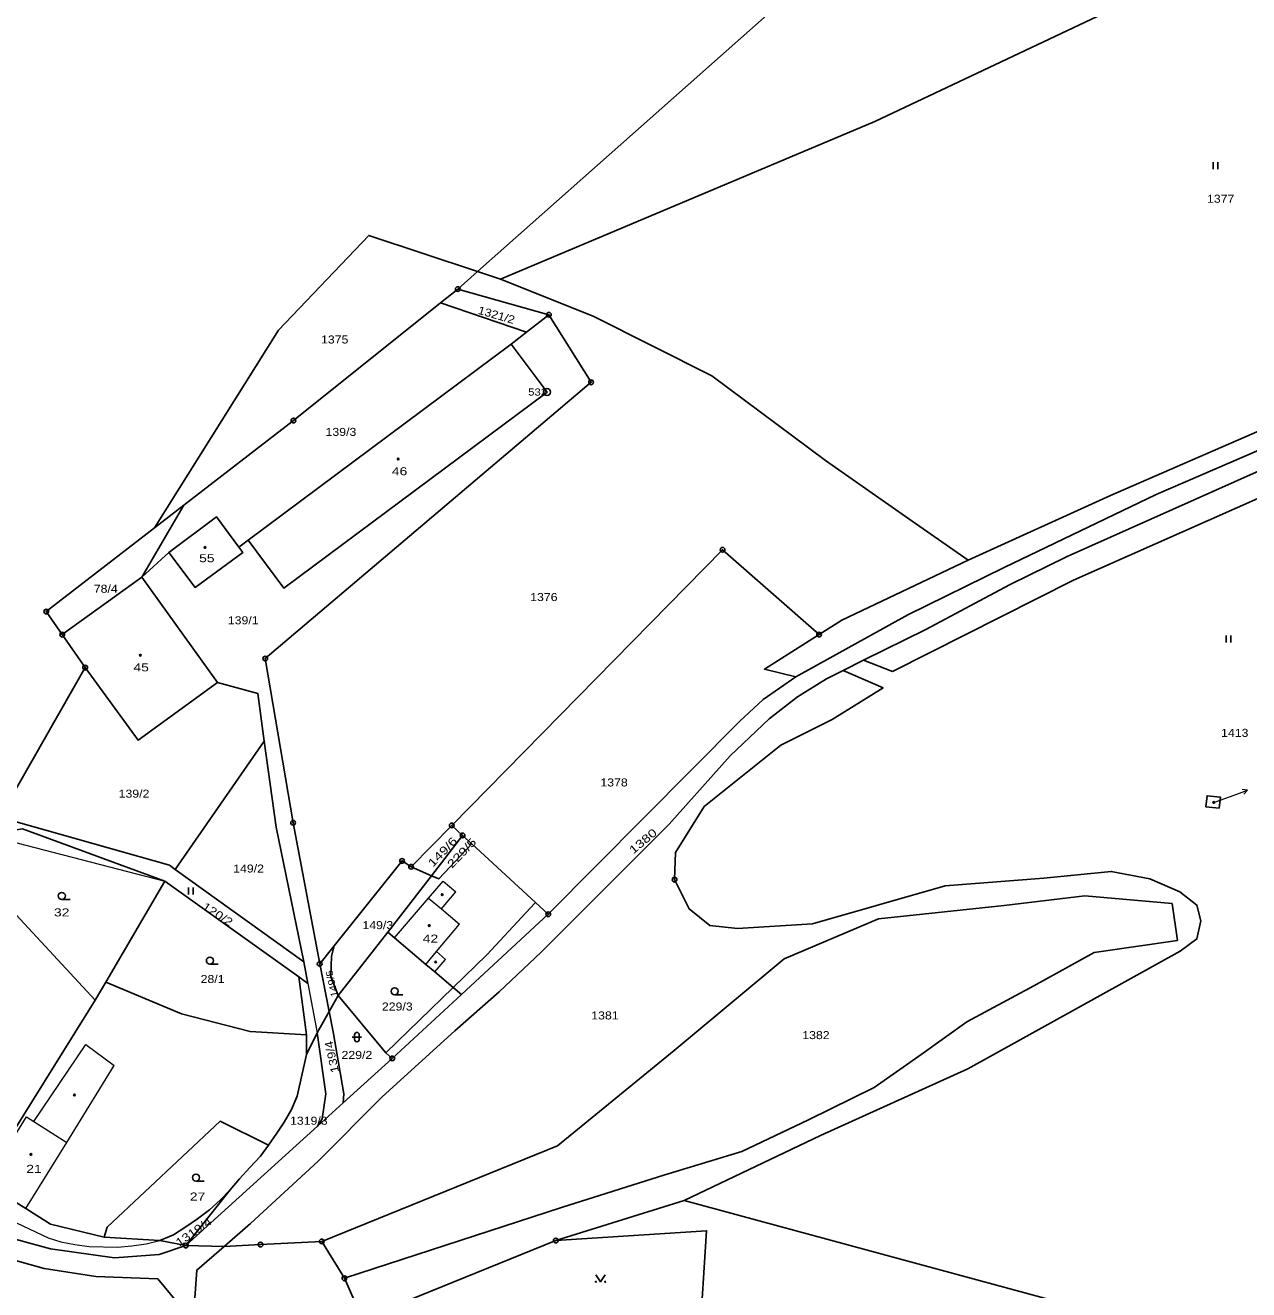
# Model space of a CAD drawing. Extents: x -872229 to -869198, y -1075981 to -1074329.
# Drawn here: x -870924.3 to -870664.3, y -1075205 to -1074936.4 of the extents above; entities that cross this region are included whole.
import ezdxf
from ezdxf.enums import TextEntityAlignment as Align

# ---------------------------------------------------------------- set-up
doc = ezdxf.new("R2010")
doc.units = 0
doc.header["$LTSCALE"] = 0.68
for name, color, linetype, lineweight in [('1', 7, 'Continuous', 25), ('3', 7, 'Continuous', 25), ('4', 7, 'Continuous', 13), ('5', 7, 'Continuous', 25), ('7', 7, 'Continuous', 13), ('8', 7, 'Continuous', 25)]:
    doc.layers.add(name, color=color, linetype=linetype, lineweight=lineweight)
doc.layers.add('2', color=7, linetype='Continuous')

msp = doc.modelspace()

# ---------------------------------------------------------------- linework, layer by layer
at = {"layer": '1'}
for p, q in [((-870832.43, -1074992.44), (-870828.23, -1074988.72)), ((-870828.23, -1074988.72), (-870823.34, -1074990.34)), ((-870832.43, -1074992.44), (-870813.05, -1074997.9)), ((-870817.8, -1075001.55), (-870836.08, -1074995.36)), ((-870821.1, -1075004.1), (-870876.96, -1075045.75)), ((-870890.62, -1075038.35), (-870899.54, -1075053.64)), ((-870896.85, -1075043.16), (-870890.62, -1075038.35)), ((-870876.96, -1075045.75), (-870878.94, -1075047.23)), ((-870893.79, -1075048.39), (-870899.54, -1075053.64)), ((-870916.45, -1075065.85), (-870911.59, -1075072.86)), ((-870837.98, -1075117.09), (-870831.39, -1075108.5)), ((-870892.44, -1075115.73), (-870865.1, -1075135.39)), ((-870837.98, -1075117.09), (-870842.32, -1075115.15)), ((-870857.82, -1075142.49), (-870847.25, -1075129.09)), ((-870858.7, -1075131.95), (-870861.76, -1075135.78)), ((-870907.21, -1075139.69), (-870909.44, -1075143.5)), ((-870857.82, -1075142.49), (-870859.76, -1075145.91)), ((-870856.75, -1075165.32), (-870846.32, -1075155.87)), ((-870862.22, -1075170.28), (-870856.75, -1075165.32)), ((-870890.21, -1075195.64), (-870862.22, -1075170.28)), ((-870880.8, -1075183.78), (-870890.21, -1075195.64)), ((-870784.32, -1075186.07), (-870610.3, -1075233.15)), ((-870907.54, -1075193.83), (-870895.75, -1075194.57)), ((-870895.75, -1075194.57), (-870890.21, -1075195.64)), ((-870890.21, -1075195.64), (-870882.08, -1075195.84)), ((-870856.49, -1075202.6), (-870861.31, -1075194.77))]:
    msp.add_line(p, q, dxfattribs=at)
for points in [[(-870828.23, -1074988.72), (-870733.1, -1074904.34), (-870634.05, -1074816.48)], [(-870823.34, -1074990.34), (-870743.76, -1074956.82), (-870646.76, -1074910.9), (-870624.12, -1074897.23)], [(-870723.96, -1075050), (-870693.71, -1075036.28), (-870649.55, -1075017.06), (-870584.14, -1074987.8), (-870552.32, -1074975.37), (-870546.15, -1074971.5), (-870542.19, -1074967.42)], [(-870896.85, -1075043.16), (-870870.5, -1075001.16), (-870851.34, -1074981.04), (-870828.23, -1074988.72)], [(-870760.55, -1075074.8), (-870736.8, -1075061.65), (-870716.28, -1075051.57), (-870684.01, -1075036.04), (-870643.52, -1075018.55), (-870612.61, -1075004.24), (-870591.23, -1074994.43), (-870570.04, -1074985.9), (-870558.3, -1074982.28), (-870544.73, -1074980.25)], [(-870746.19, -1075071.27), (-870732.98, -1075064.74), (-870715.15, -1075055.28), (-870702.93, -1075049.25), (-870662.75, -1075031.31), (-870646.95, -1075024.02), (-870627.8, -1075016.08), (-870598.46, -1075002.7), (-870582.08, -1074994.97), (-870575.53, -1074992.25), (-870561.97, -1074987.44), (-870555.39, -1074985.35), (-870547.72, -1074984.42), (-870543.16, -1074984.27), (-870536.54, -1074984.58), (-870532.83, -1074984.88), (-870528.68, -1074985.73), (-870515.43, -1074988.43), (-870489.43, -1074993.61), (-870451.62, -1074998.98)], [(-870723.96, -1075050), (-870735.85, -1075041.72), (-870754.24, -1075028.86), (-870778.4, -1075010.85), (-870803.61, -1074998.16), (-870823.34, -1074990.34)], [(-870890.62, -1075038.35), (-870867.33, -1075020.36), (-870836.08, -1074995.36), (-870832.43, -1074992.44)], [(-870861.76, -1075135.78), (-870867.42, -1075105.8), (-870873.32, -1075070.92), (-870804.09, -1075012.24), (-870813.05, -1074997.9), (-870817.8, -1075001.55), (-870821.1, -1075004.1)], [(-870876.96, -1075045.75), (-870869.36, -1075056), (-870813.44, -1075014.3), (-870821.1, -1075004.1)], [(-870746.19, -1075071.27), (-870740.01, -1075073.65), (-870701.56, -1075054.27), (-870661.14, -1075036.37), (-870626.13, -1075019.06), (-870610.36, -1075011.6)], [(-870916.45, -1075065.85), (-870919.85, -1075060.95), (-870896.85, -1075043.16)], [(-870878.94, -1075047.23), (-870883.7, -1075040.81), (-870893.79, -1075048.39)], [(-870893.79, -1075048.39), (-870888.25, -1075055.83), (-870878.08, -1075048.38), (-870878.94, -1075047.23)], [(-870833.7, -1075106.39), (-870776.15, -1075047.82), (-870755.65, -1075065.84)], [(-870755.65, -1075065.84), (-870750.79, -1075062.78), (-870723.96, -1075050)], [(-870911.59, -1075072.86), (-870900.34, -1075088.23), (-870883.44, -1075076.03), (-870899.54, -1075053.64), (-870916.45, -1075065.85)], [(-870760.55, -1075074.8), (-870767.27, -1075073.18), (-870755.65, -1075065.84)], [(-870882.08, -1075195.84), (-870876.48, -1075190.98), (-870862.11, -1075177.7), (-870848.46, -1075164.05), (-870833.06, -1075150.02), (-870823.61, -1075141.72), (-870814.66, -1075133.34), (-870787.51, -1075106.14), (-870774.51, -1075091.61), (-870766.24, -1075083.76), (-870760.23, -1075079.03), (-870754.08, -1075075.24), (-870750.53, -1075073.45), (-870746.19, -1075071.27)], [(-870930.06, -1075104.56), (-870928.47, -1075102.44), (-870911.59, -1075072.86)], [(-870813.18, -1075125.26), (-870772.47, -1075084.22), (-870767.49, -1075079.65), (-870760.55, -1075074.8)], [(-870784.32, -1075186.07), (-870755.33, -1075172.29), (-870724.06, -1075158.07), (-870678.88, -1075133.11), (-870675.36, -1075130.49), (-870674.52, -1075126.66), (-870675.34, -1075123.32), (-870678.97, -1075120.49), (-870685.35, -1075117.73), (-870693.57, -1075116.15), (-870707.89, -1075117.61), (-870728.84, -1075119.23), (-870757.05, -1075127.29), (-870772.94, -1075128.29), (-870778.87, -1075127.61), (-870783.25, -1075124.12), (-870786.34, -1075117.9), (-870786.18, -1075112.16), (-870780.09, -1075102.34), (-870763.77, -1075089.36), (-870752.86, -1075083.85), (-870742.03, -1075077.18), (-870750.53, -1075073.45)], [(-870883.44, -1075076.03), (-870874.9, -1075078.35), (-870873.52, -1075088.47)], [(-870930.06, -1075104.56), (-870893.7, -1075114.82), (-870892.44, -1075115.73), (-870873.52, -1075088.47)], [(-870873.52, -1075088.47), (-870871.03, -1075106.76), (-870865.1, -1075135.39)], [(-870894.66, -1075118.2), (-870924.88, -1075107.13), (-870932.92, -1075108.35)], [(-870858.7, -1075131.95), (-870844.26, -1075113.92), (-870842.32, -1075115.15), (-870833.7, -1075106.39)], [(-870833.7, -1075106.39), (-870831.39, -1075108.5), (-870829.44, -1075110.29)], [(-870829.44, -1075110.29), (-870836.42, -1075117.76), (-870837.98, -1075117.09)], [(-870829.44, -1075110.29), (-870815.89, -1075122.76), (-870813.18, -1075125.26)], [(-870864.56, -1075150.9), (-870866.19, -1075138.58), (-870894.66, -1075118.2), (-870907.21, -1075139.69)], [(-870837.98, -1075117.09), (-870847.25, -1075129.09), (-870845.84, -1075130.29)], [(-870909.44, -1075143.5), (-870927.17, -1075124.39), (-870932.72, -1075121.96), (-870936.66, -1075131.14), (-870945.89, -1075145.67), (-870949.71, -1075143.97), (-870951.3, -1075148.19), (-870958.37, -1075166.98), (-870949.29, -1075170.31), (-870949.89, -1075171.55)], [(-870861.31, -1075194.77), (-870811.22, -1075174.45), (-870786.41, -1075154.2), (-870763.05, -1075134.75), (-870742.98, -1075126.21), (-870716.31, -1075123.38), (-870699.19, -1075121.37), (-870680.62, -1075122.97), (-870679.5, -1075130.81), (-870697.18, -1075133.41), (-870710, -1075140.48), (-870724.25, -1075148.13), (-870733.72, -1075154.9), (-870743.9, -1075162.08), (-870757.91, -1075168.9), (-870772.04, -1075175.68), (-870788.41, -1075180.62), (-870810.37, -1075187.53), (-870856.49, -1075202.6)], [(-870813.18, -1075125.26), (-870831.64, -1075142.31), (-870846.32, -1075155.87)], [(-870845.84, -1075130.29), (-870839.22, -1075135.9), (-870837.31, -1075137.51), (-870833.4, -1075140.82), (-870831.64, -1075142.31)], [(-870857.82, -1075142.49), (-870859.36, -1075138.42), (-870859.25, -1075134.15), (-870858.7, -1075131.95)], [(-870865.1, -1075135.39), (-870864.25, -1075139.97), (-870866.19, -1075138.58)], [(-870864.56, -1075150.9), (-870864.55, -1075155.07), (-870862.32, -1075150.43), (-870859.76, -1075145.91), (-870861.76, -1075135.78)], [(-870907.21, -1075139.69), (-870891.11, -1075146.44), (-870876.55, -1075150.17), (-870864.56, -1075150.9)], [(-870846.32, -1075155.87), (-870847.68, -1075154.69), (-870857.82, -1075142.49)], [(-870949.89, -1075171.55), (-870931.15, -1075178.18), (-870909.44, -1075143.5)], [(-870856.75, -1075165.32), (-870856.65, -1075163.41), (-870858.9, -1075150.23), (-870859.76, -1075145.91)], [(-870862.32, -1075150.43), (-870860.42, -1075163.37), (-870861.23, -1075168.69), (-870862.22, -1075170.28)], [(-870890.21, -1075195.64), (-870895.9, -1075197.55), (-870905.34, -1075198.25), (-870918.98, -1075196.32), (-870930.4, -1075193.2), (-870939.76, -1075189.14), (-870966.78, -1075174.22), (-871004.43, -1075162.38), (-871023.49, -1075157.84), (-871022.7, -1075155.06)], [(-870864.55, -1075155.07), (-870866.56, -1075163.88), (-870867.75, -1075166.75), (-870869.33, -1075169.39), (-870870.88, -1075171.78), (-870872.64, -1075174.34)], [(-870907.54, -1075193.83), (-870906.89, -1075191.76), (-870882.9, -1075169.23), (-870872.64, -1075174.34)], [(-870872.64, -1075174.34), (-870874.32, -1075176.63), (-870876.57, -1075179.07), (-870878.78, -1075181.49), (-870880.8, -1075183.78)], [(-870931.15, -1075178.18), (-870930.37, -1075178.46), (-870932.82, -1075182.43), (-870924.17, -1075187.79)], [(-870880.8, -1075183.78), (-870882.93, -1075186.01), (-870885.17, -1075188.02), (-870887.7, -1075189.96), (-870890.19, -1075191.67), (-870892.85, -1075193.36), (-870895.75, -1075194.57)], [(-870924.17, -1075187.79), (-870918.98, -1075191.1), (-870907.54, -1075193.83)], [(-870852.61, -1075211.21), (-870811.58, -1075194.57), (-870784.32, -1075186.07)], [(-870811.58, -1075194.57), (-870779.53, -1075192.5), (-870781.56, -1075223.68)], [(-870882.08, -1075195.84), (-870887.87, -1075200.84), (-870890.54, -1075238.17)], [(-870861.31, -1075194.77), (-870874.33, -1075195.43), (-870882.08, -1075195.84)], [(-870925.85, -1075268.83), (-870908.47, -1075274.58), (-870898.66, -1075275.61), (-870893.76, -1075273.35), (-870892.7, -1075270.97), (-870894.88, -1075238.8), (-870892.1, -1075207.59), (-870896.18, -1075202.7), (-870909.34, -1075202.24), (-870920.27, -1075200.54), (-870931.8, -1075197.32)], [(-870852.61, -1075211.21), (-870854.23, -1075207.71), (-870856.49, -1075202.6)]]:
    msp.add_lwpolyline(points, dxfattribs=at)
msp.add_lwpolyline([(-870670.61, -1075102.74), (-870670.36, -1075100.35), (-870673.18, -1075100.06), (-870673.43, -1075102.45)], close=True, dxfattribs=at)
at = {"layer": '3'}
for p, q in [((-870671.891, -1074966.97), (-870671.891, -1074965.47)), ((-870670.89, -1074966.97), (-870670.89, -1074965.47)), ((-870669.151, -1075067.5), (-870669.151, -1075066)), ((-870668.15, -1075067.5), (-870668.15, -1075066)), ((-870889.631, -1075121.08), (-870889.631, -1075119.58)), ((-870888.63, -1075121.08), (-870888.63, -1075119.58)), ((-870916.553, -1075122.11), (-870914.803, -1075122.11)), ((-870885.093, -1075135.85), (-870883.343, -1075135.85)), ((-870845.823, -1075142.37), (-870844.073, -1075142.37)), ((-870854.861, -1075151.341), (-870852.859, -1075151.341)), ((-870854.361, -1075150.841), (-870854.361, -1075151.842)), ((-870853.359, -1075151.842), (-870853.359, -1075150.841)), ((-870888.033, -1075181.95), (-870886.283, -1075181.95))]:
    msp.add_line(p, q, dxfattribs=at)
msp.add_lwpolyline([(-870803.07, -1075201.839), (-870802.07, -1075203.34), (-870801.07, -1075201.839)], dxfattribs=at)
for centre, radius in [((-870916.5529, -1075121.3598), 0.75), ((-870885.0929, -1075135.0998), 0.75), ((-870845.8229, -1075141.6198), 0.75), ((-870888.0329, -1075181.1998), 0.75), ((-870803.07, -1075203.3395), 0.1), ((-870801.07, -1075203.3395), 0.1)]:
    msp.add_circle(centre, radius, dxfattribs=at)
for centre, start, end in [((-870853.86, -1075150.8409), 0, 180), ((-870853.86, -1075151.8409), 180, 359.98789)]:
    msp.add_arc(centre, 0.5, start, end, dxfattribs=at)
at = {"layer": '4'}
for p, q in [((-870932.92, -1075108.35), (-870894.66, -1075118.2)), ((-870838.61, -1075121.81), (-870835.53, -1075118.19)), ((-870835.53, -1075118.19), (-870832.84, -1075120.48)), ((-870835.87, -1075124.13), (-870832.84, -1075120.48)), ((-870845.84, -1075130.29), (-870838.61, -1075121.81)), ((-870838.61, -1075121.81), (-870835.87, -1075124.13)), ((-870816.01, -1075122.88), (-870815.89, -1075122.76)), ((-870835.87, -1075124.13), (-870832.06, -1075127.37)), ((-870836.91, -1075133.15), (-870832.06, -1075127.37)), ((-870839.22, -1075135.9), (-870836.91, -1075133.15)), ((-870836.91, -1075133.15), (-870835.03, -1075134.84)), ((-870837.31, -1075137.51), (-870835.03, -1075134.84)), ((-870864.25, -1075139.97), (-870862.32, -1075150.43)), ((-870847.68, -1075154.69), (-870833.4, -1075140.82)), ((-870922.52, -1075169.25), (-870911.46, -1075152.94)), ((-870911.46, -1075152.94), (-870905.41, -1075157.36)), ((-870915.47, -1075173.71), (-870905.41, -1075157.36)), ((-870930.37, -1075178.46), (-870924.07, -1075168.28)), ((-870924.17, -1075187.79), (-870915.47, -1075173.71)), ((-870936.12, -1075186.16), (-870919.45, -1075194.01)), ((-870919.45, -1075194.01), (-870916.78, -1075194.85)), ((-870916.78, -1075194.85), (-870913.82, -1075195.43)), ((-870913.82, -1075195.43), (-870910.76, -1075195.81)), ((-870910.76, -1075195.81), (-870904.71, -1075195.96)), ((-870898.65, -1075195.28), (-870895.75, -1075194.57))]:
    msp.add_line(p, q, dxfattribs=at)
for points in [[(-870833.4, -1075140.82), (-870826.26, -1075133.88), (-870816.01, -1075122.88)], [(-870924.07, -1075168.28), (-870922.52, -1075169.25), (-870915.47, -1075173.71)], [(-870904.71, -1075195.96), (-870901.65, -1075195.7), (-870898.65, -1075195.28)]]:
    msp.add_lwpolyline(points, dxfattribs=at)
at = {"layer": '5'}
for centre in [(-870845.0668, -1075028.5292), (-870886.1268, -1075047.3192), (-870899.8668, -1075070.2092), (-870671.7668, -1075101.4992), (-870835.7168, -1075121.0792), (-870838.4868, -1075127.6492), (-870837.0968, -1075135.3892), (-870913.8668, -1075163.6392), (-870923.1268, -1075176.2892)]:
    msp.add_circle(centre, 0.175, dxfattribs=at)
at = {"layer": '7'}
msp.add_line((-870664.6, -1075098.904), (-870665.712, -1075098.776), dxfattribs=at)
msp.add_lwpolyline([(-870671.43, -1075101.37), (-870667.42, -1075099.93), (-870664.6, -1075098.904), (-870665.37, -1075099.717)], dxfattribs=at)
at = {"layer": '8'}
for centre, radius in [((-870832.43, -1074992.4399), 0.5), ((-870832.43, -1074992.4399), 0.0303), ((-870813.05, -1074997.8999), 0.5), ((-870813.05, -1074997.8999), 0.0303), ((-870813.44, -1075014.2998), 0.75), ((-870804.09, -1075012.2399), 0.5), ((-870804.09, -1075012.2399), 0.0303), ((-870813.44, -1075014.2998), 0.03), ((-870867.33, -1075020.3599), 0.5), ((-870867.33, -1075020.3599), 0.0303), ((-870776.15, -1075047.8199), 0.5), ((-870776.15, -1075047.8199), 0.0303), ((-870919.85, -1075060.9499), 0.5), ((-870919.85, -1075060.9499), 0.0303), ((-870916.45, -1075065.8499), 0.5), ((-870916.45, -1075065.8499), 0.0303), ((-870755.65, -1075065.8399), 0.5), ((-870755.65, -1075065.8399), 0.0303), ((-870911.59, -1075072.8599), 0.5), ((-870873.32, -1075070.9199), 0.5), ((-870873.32, -1075070.9199), 0.0303), ((-870911.59, -1075072.8599), 0.0303), ((-870867.42, -1075105.7999), 0.5), ((-870867.42, -1075105.7999), 0.0303), ((-870833.7, -1075106.3899), 0.5), ((-870833.7, -1075106.3899), 0.0303), ((-870831.39, -1075108.4999), 0.5), ((-870831.39, -1075108.4999), 0.0303), ((-870844.26, -1075113.9199), 0.5), ((-870844.26, -1075113.9199), 0.0303), ((-870842.32, -1075115.1499), 0.5), ((-870842.32, -1075115.1499), 0.0303), ((-870786.34, -1075117.8999), 0.5), ((-870786.34, -1075117.8999), 0.0303), ((-870813.18, -1075125.2599), 0.5), ((-870813.18, -1075125.2599), 0.0303), ((-870861.76, -1075135.7799), 0.5), ((-870861.76, -1075135.7799), 0.0303), ((-870846.32, -1075155.8699), 0.5), ((-870846.32, -1075155.8699), 0.0303), ((-870890.21, -1075195.6399), 0.5), ((-870890.21, -1075195.6399), 0.0303), ((-870874.33, -1075195.4299), 0.5), ((-870874.33, -1075195.4299), 0.0303), ((-870861.31, -1075194.7699), 0.5), ((-870861.31, -1075194.7699), 0.0303), ((-870811.58, -1075194.5699), 0.5), ((-870811.58, -1075194.5699), 0.0303), ((-870856.49, -1075202.5999), 0.5), ((-870856.49, -1075202.5999), 0.0303)]:
    msp.add_circle(centre, radius, dxfattribs=at)

# ---------------------------------------------------------------- texts
at = {"layer": '2'}
for s, width, p in [('1377', 1.15, (-870673.21, -1074974.09)), ('1375', 1.15, (-870861.47, -1075003.99)), ('139/3', 1.15, (-870860.51, -1075023.62)), ('46', 1.3, (-870846.43, -1075031.98)), ('55', 1.3, (-870887.38, -1075050.46)), ('78/4', 1.15, (-870909.76, -1075056.95)), ('1376', 1.15, (-870817.03, -1075058.71)), ('139/1', 1.15, (-870881.28, -1075063.65)), ('45', 1.3, (-870901.34, -1075073.65)), ('1413', 1.15, (-870670.22, -1075087.56)), ('1378', 1.15, (-870802.11, -1075098.1)), ('139/2', 1.15, (-870904.48, -1075100.48)), ('149/2', 1.15, (-870880.14, -1075116.39)), ('32', 1.3, (-870918.22, -1075125.71)), ('149/3', 1.15, (-870852.68, -1075128.41)), ('42', 1.3, (-870839.86, -1075131.27)), ('28/1', 1.15, (-870887.06, -1075139.86)), ('229/3', 1.15, (-870848.54, -1075145.7)), ('1381', 1.15, (-870804.05, -1075147.6)), ('1382', 1.15, (-870759.21, -1075151.78)), ('229/2', 1.15, (-870857.12, -1075155.99)), ('1319/3', 1.15, (-870868.06, -1075169.97)), ('21', 1.3, (-870924.1, -1075180.19)), ('27', 1.3, (-870889.35, -1075186.07))]:
    msp.add_text(s, height=1.7, dxfattribs=dict(at, width=width)).set_placement(p)
for s, height, rotation, width, p in [('1321/2', 1.7, 344, 1.15, (-870828.274, -1074997.647)), ('1380', 1.7, 40, 1.35, (-870795.133, -1075112.571)), ('149/6', 1.7, 46, 1.35, (-870837.718, -1075115.35)), ('229/5', 1.7, 46, 1.35, (-870833.638, -1075115.59)), ('120/2', 1.7, 327, 1.25, (-870886.882, -1075124.012)), ('149/5', 1.445, 102, 1.2, (-870857.863, -1075142.699)), ('139/4', 1.7, 102, 1.2, (-870857.638, -1075158.733)), ('1319/4', 1.7, 35, 1.25, (-870891.612, -1075195.916))]:
    msp.add_text(s, height=height, rotation=rotation, dxfattribs=dict(at, width=width)).set_placement(p)
at = {"layer": '8', "width": 1.2}
msp.add_text('532', height=1.5, dxfattribs=at).set_placement((-870813.44, -1075015.05), align=Align.RIGHT)

doc.saveas('drawing.dxf')
